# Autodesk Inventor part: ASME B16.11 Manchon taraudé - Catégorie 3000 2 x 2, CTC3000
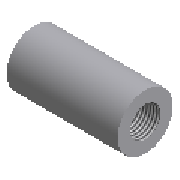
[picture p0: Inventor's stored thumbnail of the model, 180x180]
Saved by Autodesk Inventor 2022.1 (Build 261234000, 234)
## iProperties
Created: 2021-02
Part Number: ASME B16.11 Manchon taraudé - Catégorie 3000 2 x 2, CTC3000
Material: Acier
Description: Manchon taraudé - Catégorie 3000
Document SubType Name: Modeling
Standard: ASME B16.11
Designer: Fabian
Standard Revision: 2011
Standards Organization: ANSI
Language: fr-FR
Size Designation: 2 x 2
Categories: <MemberInstance><Categories><Category DisplayName="Tubes et tuyaux" InternalName="4347fa0f-2144-441d-94cd-e3e15c92b736" Mnemonic="TUBEANDPIPE"><CategoryParamete
Density: 1 g/cm^3
Appearance: Plaque
NAME: PIPING: ASME B16.11 Coupling Threaded - Class 3000
DATA: <meta><inlinegroups number="1" deflen="6.0452"></inlinegroups><connections number="2"></connections><angles><a>3.14159265358979</a></angles></meta>
IsCustomPart: 0
Author: Fabian
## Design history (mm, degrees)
sketch "Sketch1"
  geometry: L1 (0, 0)-(85.852, 0); L2 (85.852, 0)-(85.852, 28.279); L3 (85.852, 28.279)-(0, 28.279); L4 (0, 28.279)-(0, 0); L5 (85.852, 28.279)-(85.852, 38.1); L6 (85.852, 38.1)-(0, 38.1); L7 (0, 38.1)-(0, 28.279); L8 (0, 28.279)-(19.215, 27.679); L9 (42.926, 0)-(42.926, 38.1); L10 (85.852, 28.279)-(66.637, 27.679); L11 (19.215, 27.679)-(66.637, 27.679); L12 (19.215, 27.679)-(19.215, 0); L13 (66.637, 27.679)-(66.637, 0)
  constraints: 26 end point, 6 perpendicular, 2 midpoint, 2 parallel, 2 point on line, 1 horizontal, 1 symmetric about line, 1 other
  dimensions: "d0" = 56.55818 diameter of L3.end L1 (= MD); "d1" = 85.852 distance of L2.end L3.end (= W1); "d2" = 76.2 diameter of L6.end L1 (= D); "d3" = 1.78991 deg angle of L1 L8; "d4" = 19.2151 horizontal distance of L3.end L8.end (= L)
revolve "Revolve1" stored, may be unused: angle "d6" = 90 deg
workpoint "Work Point1"
workpoint "Work Point2"
workaxis "Work Axis1"
workpoint "Work Point3"
workaxis "Work Axis2"
workpoint "Work Point4"
body "Solid1"
feature "Filetage1" dims "d16" = 25.4, "d17" = 0
feature "Filetage2" dims "d18" = 25.4, "d19" = 0
other parameters: "W1" = 85.852 [user parameter; used in 1 equation term], "D" = 76.2 [user parameter; used in 1 equation term], "L" = 19.2151 [user parameter; used in 1 equation term], "MD" = 56.55818 [user parameter; used in 1 equation term], "Size_Designation" = 12.345 [user parameter]
